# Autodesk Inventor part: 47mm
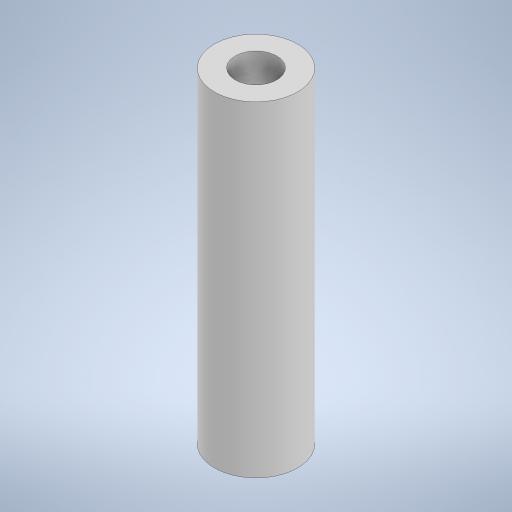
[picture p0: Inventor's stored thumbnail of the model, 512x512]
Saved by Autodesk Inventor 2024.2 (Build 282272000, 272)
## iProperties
Created: 2024-05
Part Number: 47mm
Material: Generic
Document SubType Name: Modeling
Designer: Karsten
Density: 1 g/cm^3
Appearance: Default
Author: Karsten
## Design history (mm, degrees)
sketch "Sketch1"
  geometry: C1 r 3 at (0, 0); C2 r 6 at (0, 0); 1 further point
  constraints: 2 centre point, 2 coincident
  dimensions: "d0" = 6 diameter of C1; "d1" = 12 diameter of C2
extrude "Extrusion1" new body sketch "Sketch1" distance "d2" = 47; taper "d3" = 0 deg
body "Solid1"
